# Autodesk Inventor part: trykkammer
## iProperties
Created: 2010-02
Part Number: trykkammer
Document SubType Name: Modeling
Designer: a31883
Density: 1 g/cm^3
Author: a31883
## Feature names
1. Extrusion1
